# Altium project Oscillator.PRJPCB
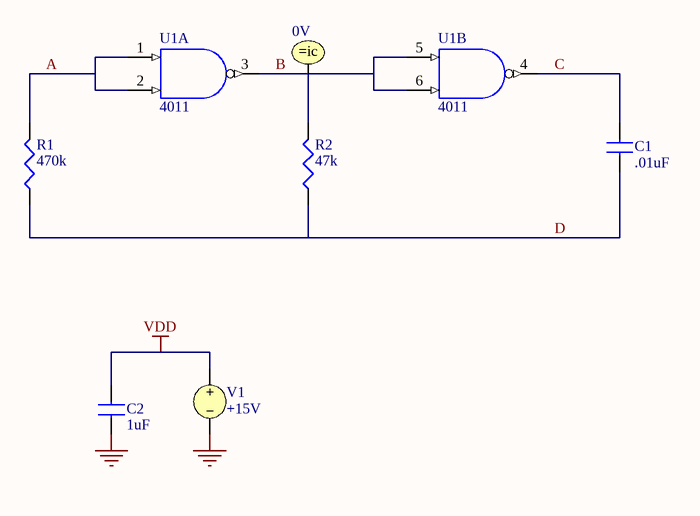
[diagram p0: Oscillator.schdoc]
1 sheet, 7 parts. Net scope: global (net labels, ports and power ports of the same name join across sheets).

## Sheet Oscillator.schdoc: Oscillator
size A4; Organization: Altium Limited; Address1: L3, 12a Rodborough Rd; Address2: Frenchs Forest; Address3: NSW; Address4: Australia 2086; DocumentNumber: 1; SheetNumber: 1; SheetTotal: 1

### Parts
C1  .01uF
C2  1uF
IC1  0V
R1  470k
R2  47k
U1  4011  (parts A,B of 4)
V1  +15V

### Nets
GND: C2.2 U1.7(GND) V1.2
VDD: C2.1 U1.14(VDD) V1.1
A: R1.1(TOP) U1.1(A) U1.2(B)
B: IC1.1 R2.1(TOP) U1.3(Y) U1.5(A) U1.6(B)
C: C1.1 U1.4(Y)
D: C1.2 R1.2(BOT) R2.2(BOT)

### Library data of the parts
C1 C2 = CAP: Capacitor
IC1 = .IC: Initial Condition
R1 R2 = RES: Resistor
U1 = 4011: Quad 2-Input NAND Gate
V1 = VSRC: Voltage Source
